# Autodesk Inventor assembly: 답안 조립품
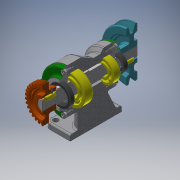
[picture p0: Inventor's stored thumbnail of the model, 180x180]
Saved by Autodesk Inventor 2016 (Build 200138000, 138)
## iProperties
Created: 2019-01
Part Number: 답안 조립품
Material: 일반
Document SubType Name: Assembly
Designer: 2-PC07
Author: 2-PC07
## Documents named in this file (15)
- C:\Users\2-PC07\Desktop\490108V1009\답안 조립품.iam
- C:\Users\2-PC07\Desktop\490108V1009\본체.ipt
- C:\Users\2-PC07\Desktop\490108V1009\베어링 6203.ipt
- C:\Users\2-PC07\Desktop\490108V1009\베어링 6205.ipt
- C:\Users\2-PC07\Desktop\490108V1009\축.ipt
- C:\Users\2-PC07\Desktop\490108V1009\앞커버.ipt
- C:\Users\2-PC07\Desktop\490108V1009\뒤커버.ipt
- C:\Users\2-PC07\Desktop\490108V1009\오일 실 25 38 8.ipt
- C:\Users\2-PC07\Desktop\490108V1009\오일 실 17 30 8.ipt
- C:\Users\2-PC07\Desktop\490108V1009\볼트 M4.ipt
- C:\Users\2-PC07\Desktop\490108V1009\키 6 x 6 x 18.ipt
- C:\Users\2-PC07\Desktop\490108V1009\키 5 x 5 x 20.ipt
- C:\Users\2-PC07\Desktop\490108V1009\스퍼기어.ipt
- C:\Users\2-PC07\Desktop\490108V1009\V-벨트풀리.ipt
- C:\Users\2-PC07\Desktop\490108V1009\멈춤나사 M3.ipt
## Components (1 placed, 1 different names)
1. V-벨트풀리:1 — 플러쉬:2
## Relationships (1: Flush 1)
- 플러쉬:2 [Flush]: V-벨트풀리:1
